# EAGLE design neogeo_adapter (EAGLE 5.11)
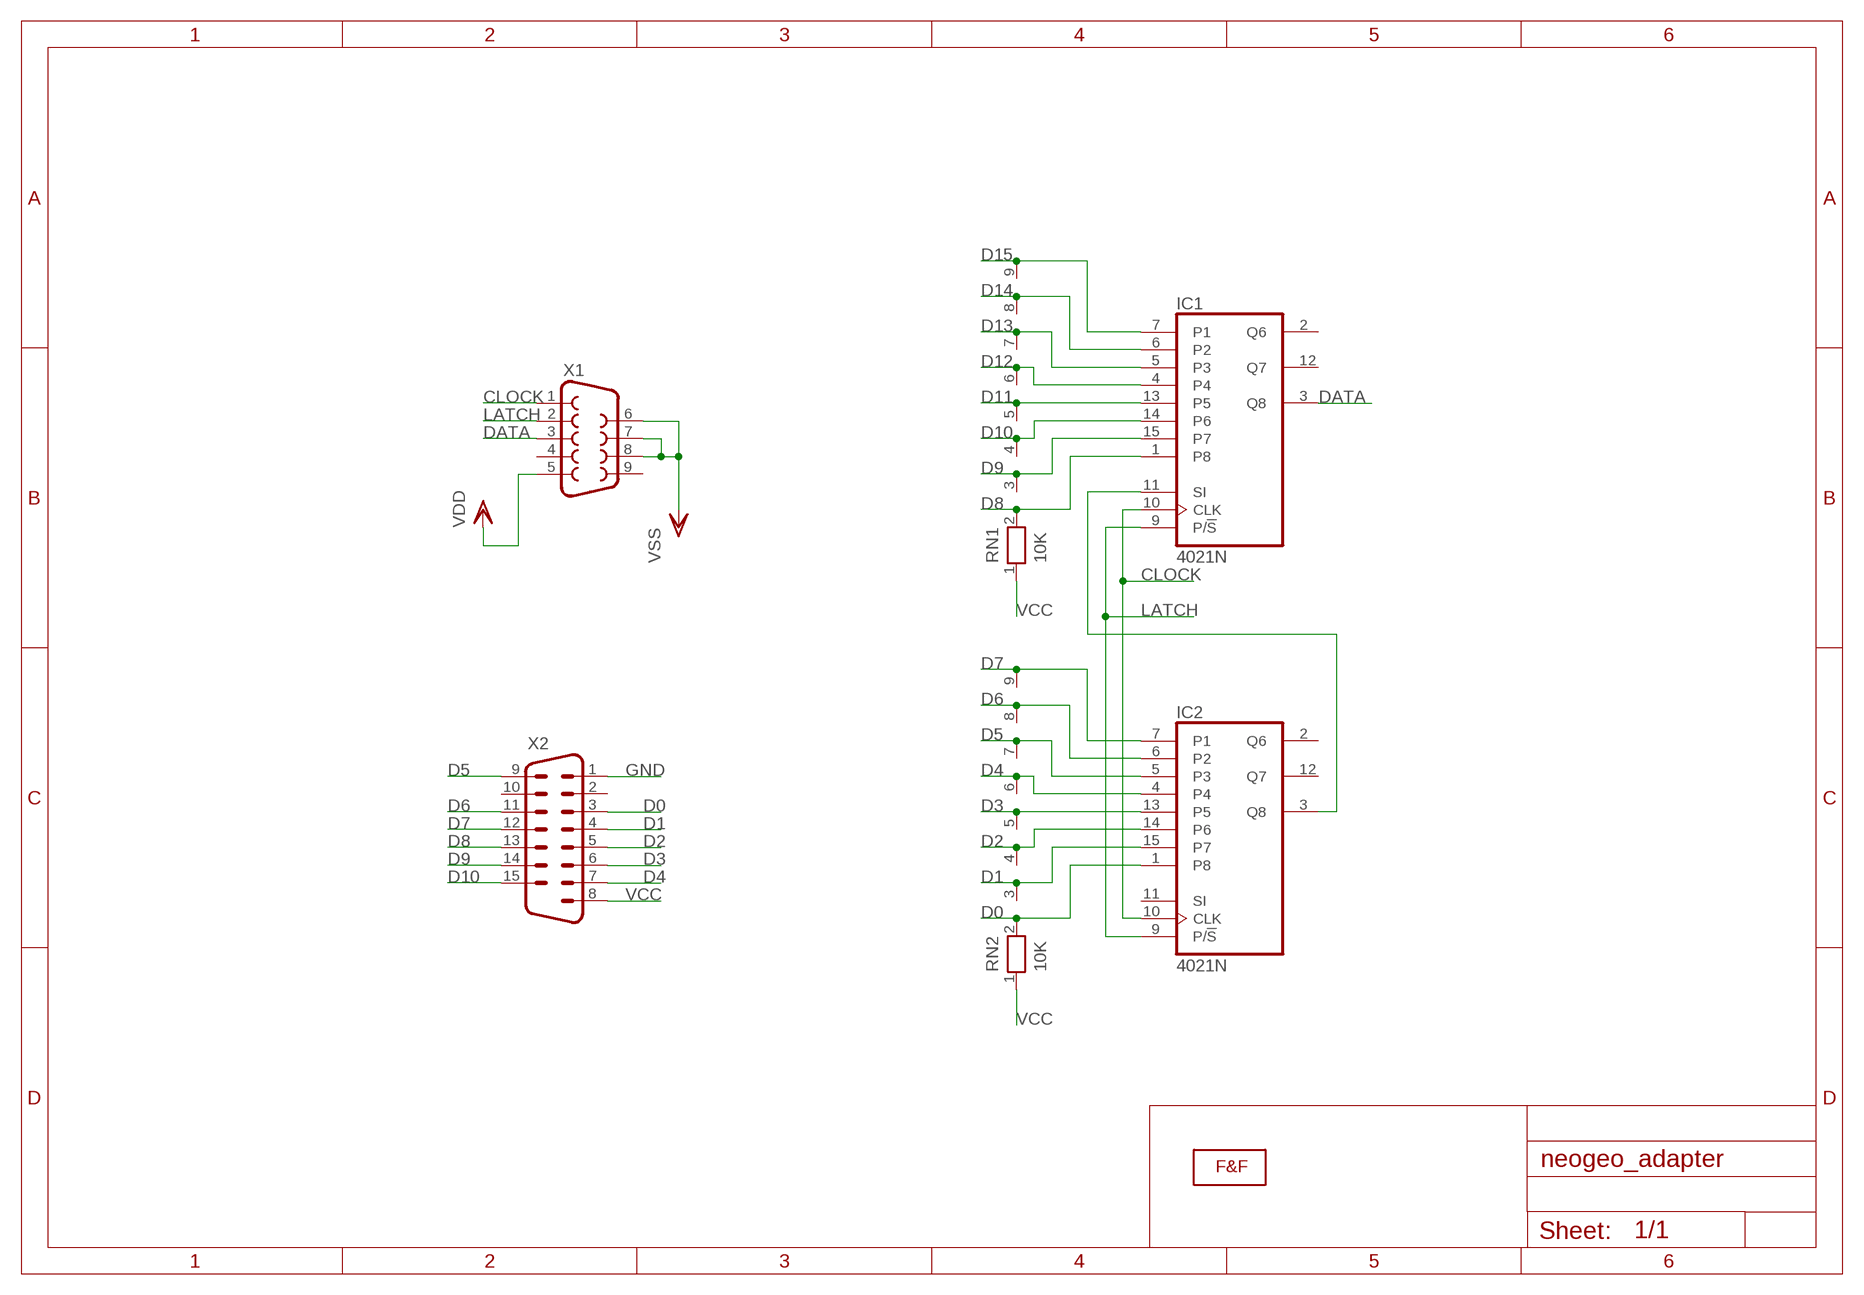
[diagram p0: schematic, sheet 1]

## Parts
IC1  4021N  [DIL16]
IC2  4021N  [DIL16]
RN1  10K  RN08  [RN-9]
RN2  10K  RN08  [RN-9]
U$1  LOGOLOGO_WITH_SMOKE_BIG  [LOGO_BIG]
X1  DB9FEMALE  [DB9]
X2  M15HP  [M15HP]

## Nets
CLOCK: IC1.10(CLK) IC2.10(CLK) X1.1
D0: IC2.1(P8) RN2.2 X2.3
D1: IC2.15(P7) RN2.3 X2.4
D2: IC2.14(P6) RN2.4 X2.5
D3: IC2.13(P5) RN2.5 X2.6
D4: IC2.4 RN2.6 X2.7
D5: IC2.5(P3) RN2.7 X2.9
D6: IC2.6(P2) RN2.8 X2.11
D7: IC2.7(P1) RN2.9 X2.12
D8: IC1.1(P8) RN1.2 X2.13
D9: IC1.15(P7) RN1.3 X2.14
D10: IC1.14(P6) RN1.4 X2.15
D11: IC1.13(P5) RN1.5
D12: IC1.4 RN1.6
D13: IC1.5(P3) RN1.7
D14: IC1.6(P2) RN1.8
D15: IC1.7(P1) RN1.9
DATA: IC1.3(Q8) X1.3
GND: X1.6 X1.7 X1.8 X2.1 ; supply symbol labelled VSS
LATCH: IC1.9(P/!S) IC2.9(P/!S) X1.2
N$19: IC1.11(SI) IC2.3(Q8)
VCC: RN1.1 RN2.1 X1.5 X2.8 ; supply symbol labelled VDD
Unconnected: IC1.2(Q6) IC1.12(Q7) IC2.2(Q6) IC2.11(SI) IC2.12(Q7) X1.4 X1.9 X2.2 X2.10

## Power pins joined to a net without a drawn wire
GND: IC1.8(VSS) IC2.8(VSS)
VCC: IC1.16(VDD) IC2.16(VDD)

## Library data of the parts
IC1 IC2 = 40xx:4021: 8-bit static SHIFT REGISTER
RN1 RN2 = resistor-net:RN08: RESISTOR NETWORK; OC_FARNELL: unknown; OC_NEWARK: unknown
U$1 = F&F:LOGO: Faísca e Fumaça Logo
X1 = SparkFun:DB9: DB9 Connector Standard DB9 (D-Sub 9) serial connector. Can be used for CAN bus as well as RS485 and RS232. Footprint production proven. Spark Fun Electronics SKU : PRT-00429
X2 = con-subd:M15: SUB-D; OC_FARNELL: unknown; OC_NEWARK: unknown

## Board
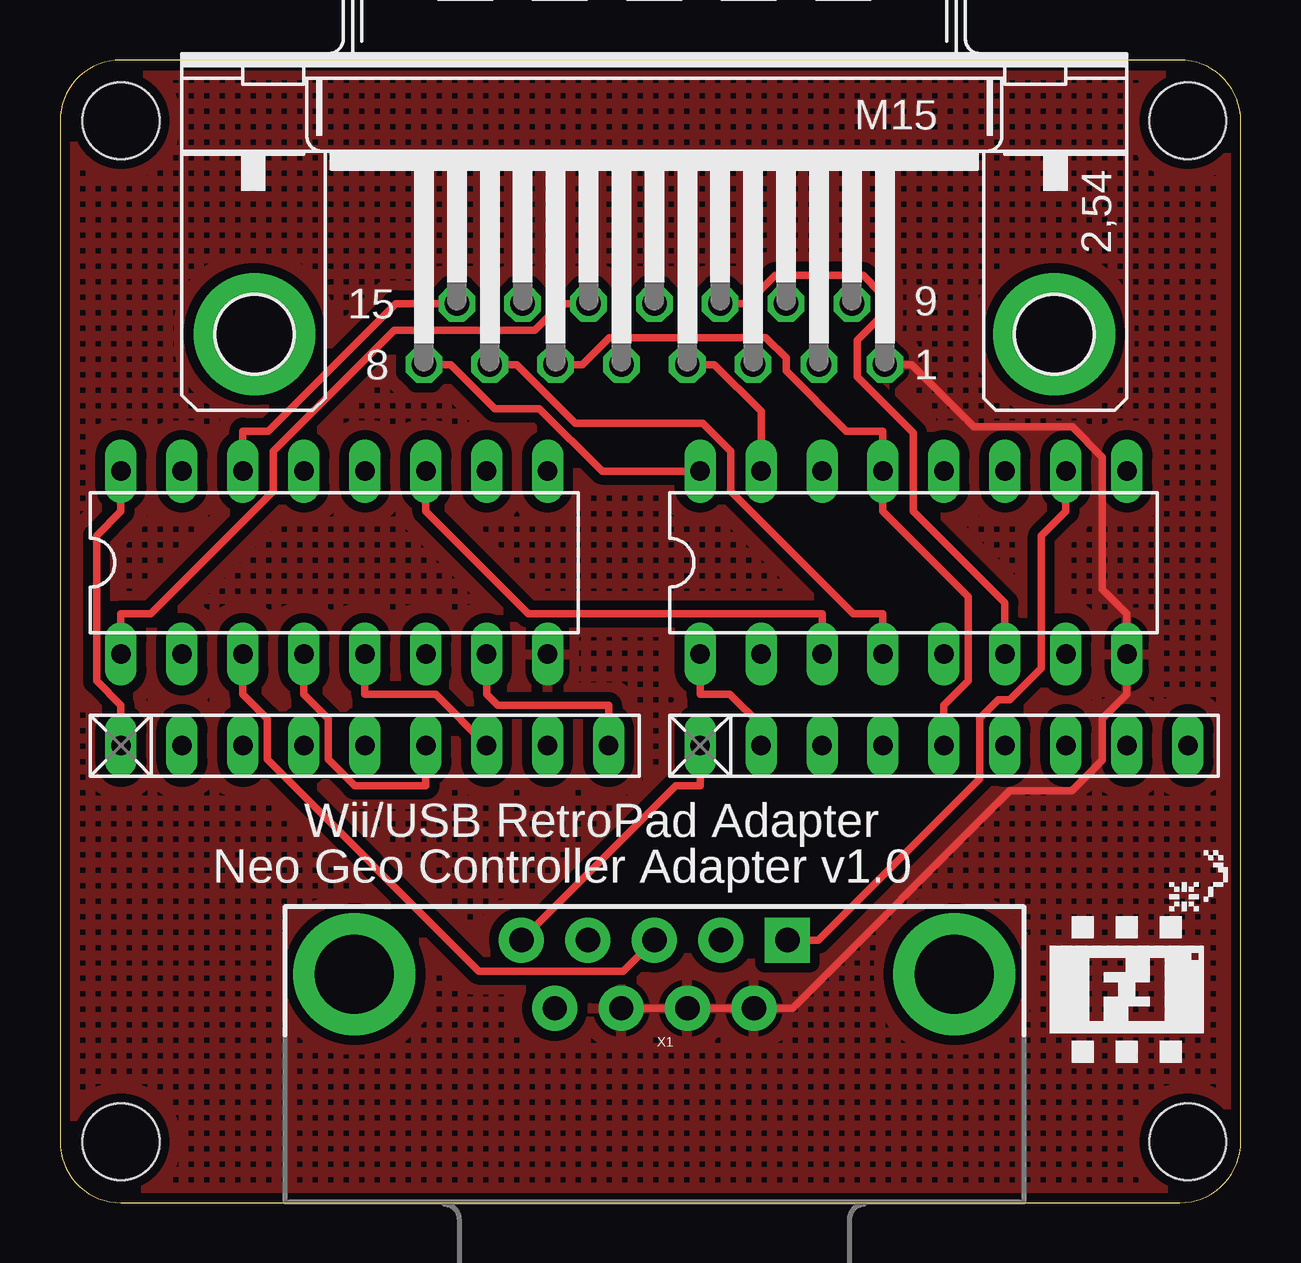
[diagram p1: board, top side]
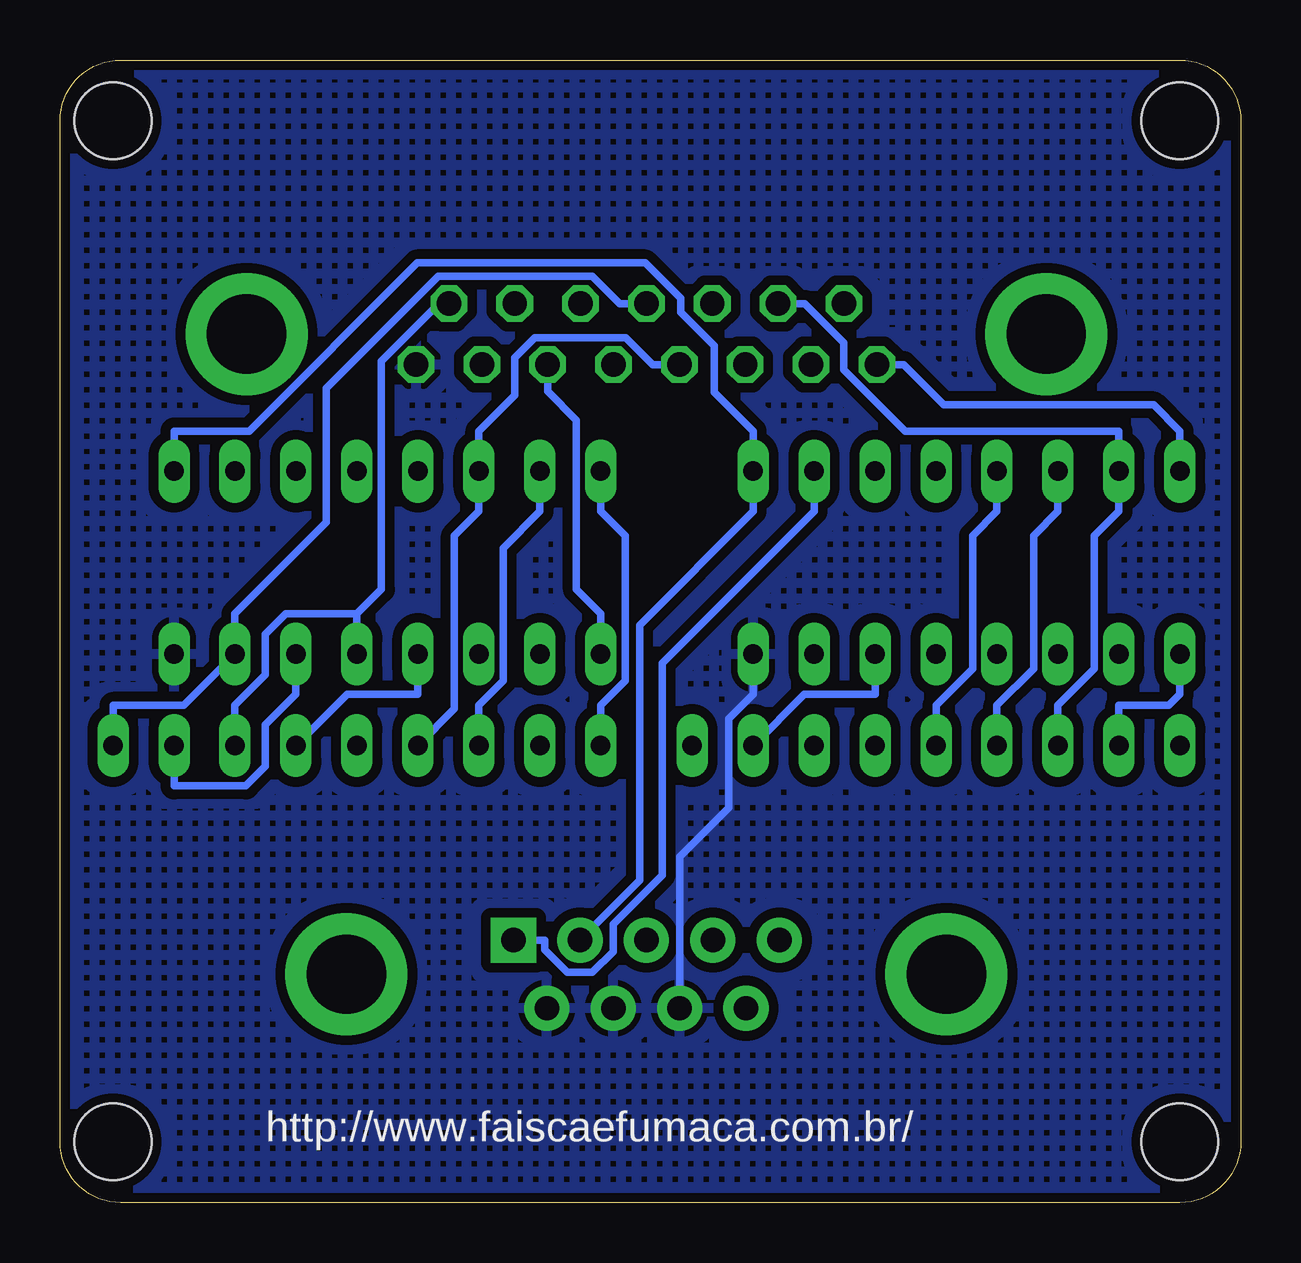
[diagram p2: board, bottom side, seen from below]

Size 49.2 x 47.62 mm. Coordinates in mm from the lower left corner, seen from the top.
Outline: 46.66,0 arc90 49.2,2.54 49.2,45.08 arc90 46.66,47.62 2.54,47.62 arc90 0,45.08 0,2.54 arc90 2.54,0 46.66,0
Copper layers (1*16): Top 0.035mm / dielectric 1.5mm / Bottom 0.035mm
Design rules "ITead_rule": minimum track width 6mil, minimum drill 12mil, track to track 6mil, track to pad 6mil, pad to pad 6mil, via to via 6mil, smd to smd 0mil, copper to edge 10mil, drill to drill 10mil, minimum pad ring 10mil, minimum via ring 6mil, stop-mask expansion 2mil, vias tented up to drill 100mil, thermal gap 10mil
Holes 3.2 mm at 2.54,45.09 46.99,45.09 2.54,2.54 46.99,2.54

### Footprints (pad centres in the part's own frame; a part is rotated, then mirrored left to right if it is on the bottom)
DIL16 = drill 0.813 long: 1 -8.89,-3.81; 2 -6.35,-3.81; 3 -3.81,-3.81; 4 -1.27,-3.81; 5 1.27,-3.81; 6 3.81,-3.81; 7 6.35,-3.81; 8 8.89,-3.81; 9 8.89,3.81; 10 6.35,3.81; 11 3.81,3.81; 12 1.27,3.81; 13 -1.27,3.81; 14 -3.81,3.81; 15 -6.35,3.81; 16 -8.89,3.81
RN-9 = drill 0.813 long: 1 -10.16,0; 2 -7.62,0; 3 -5.08,0; 4 -2.54,0; 5 0,0; 6 2.54,0; 7 5.08,0; 8 7.62,0; 9 10.16,0
DB9 = drill 1.016 pad 1.88 square: 1 -5.54,-1.42 | drill 1.016 pad 1.88 round: 2 -2.77,-1.42; 3 0,-1.42; 4 2.77,-1.42; 5 5.54,-1.42; 6 -4.15,1.42; 7 -1.38,1.42; 8 1.38,1.42; 9 4.15,1.42 | drill 3.302 pad 5.08 round: G1 -12.5,0; G2 12.5,0
M15HP = drill 1.016 octagon: 1 -9.601,1.27; 2 -6.858,1.27; 3 -4.115,1.27; 4 -1.372,1.27; 5 1.372,1.27; 6 4.115,1.27; 7 6.858,1.27; 8 9.601,1.27; 9 -8.23,-1.27; 10 -5.486,-1.27; 11 -2.743,-1.27; 12 0,-1.27; 13 2.743,-1.27; 14 5.486,-1.27; 15 8.23,-1.27 | drill 3.302 pad 5.08 round: G1 -16.662,0; G2 16.662,0

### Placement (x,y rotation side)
IC1  11.43,26.67 0 top
IC2  35.56,26.67 0 top
RN1  12.7,19.05 0 top
RN2  36.83,19.05 0 top
U$1  44.45,8.89 0 top
X1  24.77,9.53 180 top
X2  24.77,36.2 180 top

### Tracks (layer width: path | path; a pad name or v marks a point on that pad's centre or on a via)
CLOCK
  Top 0.305: IC2.10 41.91,28.8 40.89,27.79 40.89,22.27 39.58,20.95 39.1,20.95 38.33,20.18 38.33,17.67 31.6,10.95 X1.1
  Bottom 0.305: IC1.10 17.78,28.8 24.11,22.48 24.11,13.65 26.15,11.61 26.15,10.47 27.01,9.6 28.07,9.6 29.01,10.54 29.01,10.95 X1.1
D0
  Top 0.305: IC2.1 26.67,21.18 27.91,21.18 29.21,19.89 RN2.2
  Bottom 0.305: IC2.1 26.67,24.54 27.69,25.55 27.69,32.61 28.88,33.81 X2.3
D1
  Top 0.305: X2.4 27.25,34.92 29.21,32.97 29.21,32.16 IC2.15
  Bottom 0.305: RN2.3 31.75,20.73 30.73,21.74 30.73,27.28 29.21,28.8 IC2.15
D2
  Bottom 0.305: X2.5 24.51,34.92 25.63,36.04 29.41,36.04 30.25,35.2 30.25,33.66 31.75,32.16 IC2.14 31.75,28.8 32.77,27.79 32.77,20.57 RN2.4
D3
  Top 0.305: RN2.5 36.83,20.73 37.85,21.74 37.85,25.25 34.29,28.8 IC2.13 34.29,32.16 32.76,32.16 30.25,34.66 30.25,35.2 29.41,36.04 22.89,36.04 21.77,34.92 X2.6
D4
  Top 0.305: IC2.4 34.29,24.54 33.05,24.54 27.94,29.65 27.94,31.32 26.79,32.47 21.48,32.47 19.02,34.92 X2.7
  Bottom 0.305: IC2.4 34.29,21.18 37.24,21.18 RN2.6
D5
  Bottom 0.305: RN2.7 41.91,20.73 40.64,22 40.64,23.69 39.8,24.54 36.83,24.54 | 36.83,24.54 IC2.5 | X2.9 33.42,37.47 35.81,35.07 35.81,25.55 36.83,24.54
D6
  Top 0.305: X2.11 28.63,37.47 29.8,38.64 33.46,38.64 34.16,37.94 34.16,36.88 33.23,35.94 33.23,34.41 35.56,32.08 35.56,28.8 39.37,24.99 IC2.6
  Bottom 0.305: RN2.8 44.45,17.37 41.46,17.37 40.64,18.19 40.64,19.91 39.37,21.18 IC2.6
D7
  Bottom 0.305: X2.12 25.88,37.47 27.02,38.61 33.44,38.61 38.1,33.95 38.1,28.35 41.91,24.54 IC2.7 44.04,20.73 46.99,20.73 RN2.9
D8
  Top 0.305: IC1.1 2.54,24.54 3.78,24.54 8.89,29.65 8.89,31.32 13.92,36.35 19.79,36.35 20.9,37.47 X2.13
  Bottom 0.305: IC1.1 2.54,21.18 3,20.73 5.08,20.73 RN1.2
D9
  Bottom 0.305: X2.14 18.16,37.47 16.54,35.84 16.54,34.71 13.98,32.16 5.08,32.16 IC1.15 5.08,28.8 6.1,27.79 6.1,22.25 7.62,20.73 RN1.3
D10
  Top 0.305: X2.15 15.42,37.47 13.98,37.47 8.67,32.16 7.62,32.16 IC1.14
  Bottom 0.305: IC1.14 7.62,28.8 8.64,27.79 8.64,22.25 10.16,20.73 RN1.4
D11
  Bottom 0.305: IC1.13 10.16,28.8 11.18,27.79 11.18,22.25 12.7,20.73 RN1.5
D12
  Top 0.305: IC1.4 10.16,21.18 11.18,20.17 11.18,18.48 12.28,17.37 15.24,17.37 RN1.6
D13
  Top 0.305: IC1.5 12.7,21.18 15.65,21.18 RN1.7
D14
  Bottom 0.305: IC1.6 15.24,21.18 18.19,21.18 RN1.8
D15
  Top 0.305: IC1.7 17.78,21.18 18.24,20.73 22.86,20.73 RN1.9
DATA
  Top 0.305: IC1.3 7.62,21.18 8.64,20.17 8.64,18.47 17.46,9.65 23.47,9.65 X1.3
GND
  Top 0.305: X2.1 35.48,34.92 38.08,32.33 42.17,32.33 43.43,31.06 43.43,25.55 44.45,24.54 IC2.8 44.45,21.18 43.43,20.17 43.43,18.45 42.15,17.16 39.58,17.16 30.52,8.11 X1.6 X1.7 X1.8
  Bottom 0.305: IC1.8 20.32,21.18 21.34,20.17 21.34,16.47 23.39,14.42 X1.8
  pour Top (isolate 0.406, hatched): 0,46.99 49.53,46.99 49.53,0 0,0
  pour Bottom (isolate 0.406, hatched): 0,46.99 49.53,46.99 49.53,0 0,0
LATCH
  Bottom 0.305: X1.2 25.05,13.43 25.05,24.07 20.32,28.8 IC1.9 20.32,32.16 21.93,33.77 21.93,35.7 23.34,37.11 23.34,37.68 24.82,39.16 34.32,39.16 41.32,32.16 44.45,32.16 IC2.9
N$19
  Top 0.305: IC1.11 15.24,28.8 19.51,24.54 31.75,24.54 IC2.3
VCC
  Top 0.305: IC2.16 22.58,30.48 19.98,33.09 18.12,33.09 16.28,34.92 X2.8 | RN2.1 26.67,17.37 25.65,17.37 X1.5 | IC1.16 2.54,28.8 1.52,27.79 1.52,21.74 2.54,20.73 RN1.1
  Bottom 0.305: IC1.16 2.54,32.16 3.63,33.25 12.37,33.25 14.05,34.92 X2.8 | IC2.16 26.67,28.8 25.65,27.79 25.65,21.74 26.67,20.73 RN2.1

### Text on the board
tPlace: Wii/USB RetroPad Adapter | Neo Geo Controller Adapter v1.0
bPlace: http://www.faiscaefumaca.com.br/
